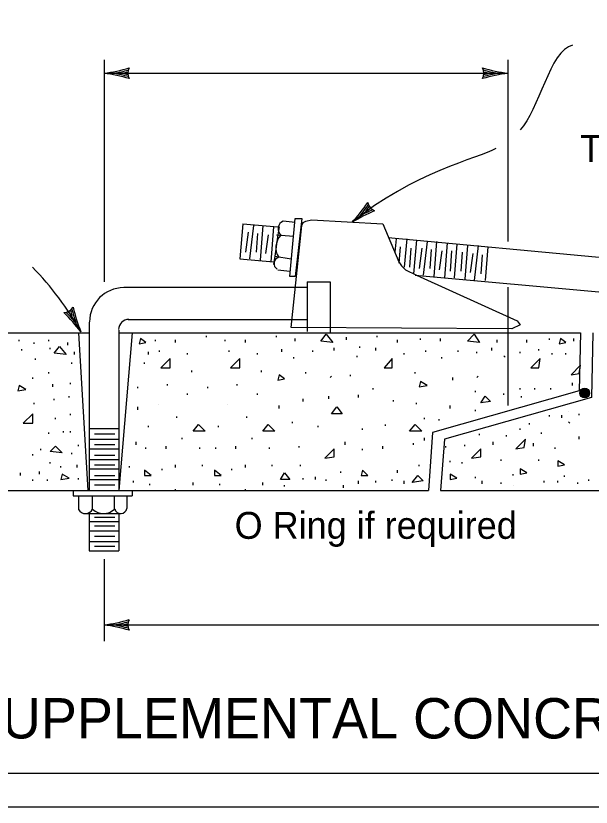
# Model space of a CAD drawing. Extents: x 0 to 390, y 0 to 265.
# Drawn here: x 134.4 to 177.2, y 0 to 58.8 of the extents above; entities that cross this region are included whole.
import ezdxf

# ---------------------------------------------------------------- set-up
doc = ezdxf.new("R2010")
doc.units = 0
doc.layers.add('D_Details', color=7, linetype='Continuous')
doc.layers.add('Default', color=7, linetype='Continuous')

msp = doc.modelspace()

# ---------------------------------------------------------------- linework, layer by layer
at = {"layer": 'D_Details'}
for p, q in [((140.967, 55.541), (140.967, 39.041)), ((170.967, 55.541), (170.967, 42.041)), ((140.967, 54.541), (170.967, 54.541)), ((151.267, 43.341), (151.067, 40.741)), ((151.267, 43.341), (153.867, 43.141)), ((152.067, 43.241), (151.767, 40.741)), ((152.767, 43.241), (152.567, 40.641)), ((153.567, 43.141), (153.367, 40.541)), ((151.667, 42.741), (151.467, 41.241)), ((152.367, 42.641), (152.267, 41.241)), ((153.167, 42.541), (152.967, 41.141)), ((153.767, 42.541), (155.067, 42.441)), ((162.067, 42.341), (200.667, 38.741)), ((162.667, 42.241), (162.567, 41.241)), ((163.467, 42.241), (163.267, 40.141)), ((164.167, 42.141), (163.967, 39.641)), ((164.967, 42.041), (164.667, 39.541)), ((165.667, 42.041), (165.467, 39.441)), ((166.467, 41.941), (166.267, 39.341)), ((167.167, 41.841), (166.967, 39.341)), ((162.967, 41.641), (162.867, 40.441)), ((163.767, 41.541), (163.667, 40.141)), ((164.567, 41.541), (164.367, 40.041)), ((165.267, 41.441), (165.167, 40.041)), ((166.067, 41.341), (165.867, 39.941)), ((166.767, 41.341), (166.667, 39.841)), ((167.567, 41.241), (167.467, 39.841)), ((167.967, 41.741), (167.767, 39.241)), ((168.767, 41.741), (168.467, 39.141)), ((169.467, 41.641), (169.267, 39.141)), ((151.067, 40.741), (153.567, 40.541)), ((153.667, 40.941), (154.867, 40.741)), ((168.367, 41.141), (168.167, 39.741)), ((169.067, 41.041), (168.967, 39.641)), ((164.067, 39.541), (200.067, 36.241)), ((156.067, 39.041), (157.767, 39.041)), ((156.067, 39.041), (156.067, 35.641)), ((157.767, 39.041), (157.767, 35.641)), ((142.467, 38.641), (155.167, 38.641)), ((155.167, 38.641), (156.067, 38.641)), ((170.967, 38.641), (170.967, 29.841)), ((139.867, 36.041), (139.867, 23.541)), ((142.767, 36.241), (154.967, 36.241)), ((154.967, 36.241), (156.067, 36.241)), ((142.067, 35.441), (142.067, 23.541)), ((156.067, 35.641), (156.067, 35.341)), ((157.767, 35.641), (157.767, 35.241)), ((127.267, 35.241), (139.867, 35.241)), ((134.667, 34.641), (134.667, 34.741)), ((136.867, 34.641), (136.867, 34.741)), ((139.067, 35.241), (139.767, 23.541)), ((143.067, 35.241), (142.067, 23.541)), ((142.067, 35.241), (176.367, 35.241)), ((144.779, 34.641), (144.779, 34.741)), ((146.279, 34.541), (146.279, 34.741)), ((148.579, 34.941), (148.579, 35.041)), ((149.967, 34.641), (149.967, 34.741)), ((151.467, 34.541), (151.467, 34.741)), ((153.767, 34.941), (153.767, 35.041)), ((155.167, 34.641), (155.167, 34.841)), ((158.967, 34.741), (158.967, 34.941)), ((161.267, 34.941), (161.267, 35.041)), ((162.767, 34.541), (162.767, 34.741)), ((164.467, 34.741), (164.467, 34.841)), ((165.967, 34.641), (165.967, 34.841)), ((170.167, 34.541), (170.167, 34.741)), ((172.367, 34.541), (172.367, 34.741)), ((174.067, 34.741), (174.067, 34.841)), ((175.867, 34.641), (175.867, 34.841)), ((135.767, 34.441), (135.767, 34.541)), ((136.967, 34.041), (136.967, 34.141)), ((138.267, 34.341), (138.267, 34.541)), ((158.067, 33.941), (158.067, 34.141)), ((159.967, 34.141), (159.967, 34.241)), ((161.167, 33.941), (161.167, 34.141)), ((169.767, 33.941), (169.767, 34.141)), ((134.867, 33.941), (134.867, 34.041)), ((138.767, 33.641), (138.767, 33.841)), ((144.267, 33.641), (144.267, 33.841)), ((145.079, 33.841), (145.079, 33.941)), ((147.179, 33.641), (147.179, 33.741)), ((150.267, 33.841), (150.267, 33.941)), ((152.367, 33.641), (152.367, 33.741)), ((154.167, 33.841), (154.167, 34.041)), ((156.467, 33.841), (156.467, 33.941)), ((159.767, 33.441), (159.767, 33.541)), ((163.267, 33.641), (163.267, 33.741)), ((164.867, 33.841), (164.867, 33.941)), ((167.267, 33.841), (167.267, 33.941)), ((168.667, 33.741), (168.667, 33.841)), ((170.767, 33.441), (170.667, 33.541)), ((171.867, 33.741), (171.867, 33.841)), ((173.267, 33.941), (173.267, 34.041)), ((174.267, 33.641), (174.267, 33.741)), ((175.267, 33.641), (175.267, 33.741)), ((135.867, 33.241), (135.867, 33.341)), ((138.567, 32.941), (138.567, 33.041)), ((143.967, 32.941), (143.967, 33.041)), ((155.067, 33.341), (155.067, 33.441)), ((166.067, 33.341), (166.067, 33.441)), ((147.479, 32.341), (147.479, 32.441)), ((152.667, 32.341), (152.667, 32.441)), ((135.667, 31.841), (135.667, 31.941)), ((136.867, 32.241), (136.867, 32.341)), ((155.967, 32.241), (155.967, 32.341)), ((157.767, 31.941), (157.867, 32.041)), ((159.267, 32.041), (159.267, 32.141)), ((164.067, 32.241), (164.067, 32.341)), ((166.867, 31.741), (166.867, 31.941)), ((168.667, 31.941), (168.767, 32.041)), ((137.167, 31.241), (137.167, 31.441)), ((138.467, 31.441), (138.467, 31.541)), ((143.479, 31.141), (143.479, 31.241)), ((145.679, 31.341), (145.679, 31.441)), ((148.667, 31.141), (148.667, 31.241)), ((150.867, 31.341), (150.867, 31.441)), ((175.767, 31.341), (175.767, 31.541)), ((147.179, 30.641), (147.179, 30.741)), ((152.367, 30.641), (152.367, 30.741)), ((159.867, 30.441), (159.867, 30.641)), ((160.967, 31.041), (160.967, 31.141)), ((168.567, 30.841), (168.567, 30.941)), ((170.667, 30.641), (170.667, 30.741)), ((171.867, 31.041), (171.867, 31.141)), ((172.967, 31.041), (172.967, 31.141)), ((174.167, 31.041), (174.167, 31.141)), ((135.767, 29.941), (135.767, 30.041)), ((137.267, 30.241), (137.267, 30.341)), ((138.367, 30.441), (138.367, 30.541)), ((155.767, 30.141), (155.767, 30.341)), ((157.667, 30.341), (157.667, 30.541)), ((162.467, 30.141), (162.467, 30.241)), ((164.167, 29.941), (164.167, 30.041)), ((171.967, 30.441), (171.967, 30.541)), ((143.467, 29.541), (143.467, 29.741)), ((144.979, 29.941), (144.979, 29.941)), ((150.167, 29.941), (150.167, 29.941)), ((153.967, 29.641), (153.967, 29.841)), ((166.667, 29.641), (166.667, 29.841)), ((168.567, 29.441), (168.567, 29.541)), ((175.467, 29.441), (175.467, 29.441)), ((137.367, 28.841), (137.367, 28.941)), ((138.467, 29.141), (138.467, 29.241)), ((146.379, 28.941), (146.379, 29.041)), ((151.567, 28.941), (151.567, 29.041)), ((164.767, 28.841), (164.767, 28.941)), ((165.867, 28.741), (165.867, 28.841)), ((174.067, 29.041), (174.067, 29.141)), ((174.967, 28.941), (174.967, 29.141)), ((176.267, 29.141), (176.267, 29.241)), ((144.279, 28.241), (144.279, 28.341)), ((149.467, 28.241), (149.467, 28.341)), ((154.967, 28.541), (154.967, 28.641)), ((156.867, 28.241), (156.867, 28.341)), ((161.867, 28.341), (161.867, 28.441)), ((172.567, 28.441), (172.567, 28.541)), ((175.567, 28.541), (175.467, 28.641)), ((136.867, 27.741), (136.867, 27.841)), ((137.967, 27.841), (137.967, 27.941)), ((138.467, 27.841), (138.467, 27.941)), ((139.867, 28.141), (142.067, 28.141)), ((140.267, 27.752), (141.767, 27.752)), ((160.167, 28.041), (160.167, 28.141)), ((168.867, 27.641), (168.867, 27.741)), ((171.867, 28.041), (171.867, 28.141)), ((173.467, 27.741), (173.467, 27.841)), ((139.867, 27.341), (142.067, 27.341)), ((143.367, 26.941), (143.367, 27.141)), ((146.779, 27.341), (146.779, 27.441)), ((151.967, 27.341), (151.967, 27.441)), ((158.867, 26.941), (158.867, 27.141)), ((164.767, 27.241), (164.767, 27.441)), ((169.867, 26.941), (169.867, 27.141)), ((170.867, 27.541), (170.867, 27.641)), ((176.267, 27.341), (176.267, 27.541)), ((136.267, 26.541), (136.267, 26.641)), ((139.067, 26.841), (139.067, 26.941)), ((139.867, 26.641), (142.067, 26.641)), ((140.267, 26.952), (141.767, 26.952)), ((144.079, 26.641), (144.079, 26.741)), ((145.579, 26.641), (145.579, 26.841)), ((148.079, 26.641), (148.079, 26.741)), ((149.267, 26.641), (149.267, 26.741)), ((150.767, 26.641), (150.767, 26.841)), ((153.267, 26.641), (153.267, 26.741)), ((155.467, 26.741), (155.467, 26.841)), ((160.167, 26.541), (160.167, 26.641)), ((161.667, 26.641), (161.667, 26.841)), ((163.967, 26.941), (163.967, 27.041)), ((166.367, 26.741), (166.367, 26.841)), ((167.767, 26.841), (167.767, 26.941)), ((172.867, 26.841), (172.867, 27.041)), ((174.467, 26.641), (174.467, 26.741)), ((135.667, 26.141), (135.667, 26.241)), ((138.567, 26.241), (138.567, 26.341)), ((140.267, 26.152), (141.767, 26.152)), ((136.967, 25.541), (136.967, 25.641)), ((137.767, 25.241), (137.767, 25.341)), ((138.967, 25.241), (138.967, 25.441)), ((139.867, 25.841), (142.067, 25.841)), ((140.267, 25.452), (141.767, 25.452)), ((142.867, 25.241), (142.867, 25.341)), ((146.279, 25.241), (146.279, 25.441)), ((148.279, 25.341), (148.279, 25.441)), ((151.467, 25.241), (151.467, 25.441)), ((153.467, 25.341), (153.467, 25.441)), ((155.567, 25.341), (155.567, 25.441)), ((164.367, 25.341), (164.367, 25.441)), ((166.667, 25.641), (166.667, 25.741)), ((167.567, 25.541), (167.567, 25.641)), ((170.467, 25.741), (170.467, 25.841)), ((173.267, 25.741), (173.267, 25.841)), ((134.767, 24.641), (134.767, 24.841)), ((136.167, 24.741), (136.167, 24.941)), ((139.867, 25.141), (142.067, 25.141)), ((145.279, 25.041), (145.279, 25.141)), ((150.467, 25.041), (150.467, 25.141)), ((158.567, 24.841), (158.567, 24.941)), ((162.767, 24.841), (162.767, 25.041)), ((171.367, 24.641), (171.367, 24.741)), ((135.667, 24.241), (135.667, 24.341)), ((136.767, 24.241), (136.767, 24.341)), ((139.067, 24.341), (139.067, 24.441)), ((139.867, 24.341), (142.067, 24.341)), ((140.267, 24.652), (141.767, 24.652)), ((143.167, 24.141), (143.167, 24.241)), ((147.579, 23.941), (147.579, 24.141)), ((152.767, 23.941), (152.767, 24.141)), ((155.767, 24.341), (155.767, 24.441)), ((156.667, 24.341), (156.667, 24.541)), ((157.467, 24.241), (157.467, 24.341)), ((159.867, 24.041), (159.867, 24.241)), ((161.167, 24.141), (161.167, 24.241)), ((162.367, 24.241), (162.367, 24.341)), ((163.267, 24.041), (163.267, 24.241)), ((168.567, 24.441), (168.567, 24.541)), ((169.067, 24.041), (169.067, 24.241)), ((170.467, 24.041), (170.467, 24.141)), ((173.667, 24.141), (173.667, 24.241)), ((174.667, 24.141), (174.667, 24.241)), ((175.167, 24.541), (175.167, 24.641)), ((176.167, 24.041), (176.167, 24.141)), ((176.967, 24.241), (176.967, 24.341)), ((127.267, 23.541), (165.067, 23.541)), ((138.667, 23.541), (143.067, 23.541)), ((138.667, 23.541), (138.667, 23.141)), ((139.967, 23.541), (142.067, 23.541)), ((140.267, 23.952), (141.767, 23.952)), ((143.067, 23.541), (143.067, 23.141)), ((144.379, 23.941), (144.379, 24.041)), ((146.279, 23.541), (146.279, 23.641)), ((149.567, 23.941), (149.567, 24.041)), ((151.467, 23.541), (151.467, 23.641)), ((154.367, 23.841), (154.367, 23.941)), ((158.767, 23.741), (158.767, 23.941)), ((165.967, 23.541), (212.067, 23.541)), ((171.367, 23.941), (171.367, 23.941)), ((138.667, 23.141), (143.067, 23.141)), ((139.067, 23.141), (139.067, 22.117)), ((140.12, 22.152), (140.12, 23.141)), ((141.757, 22.173), (141.757, 23.141)), ((142.667, 23.141), (142.667, 22.205)), ((139.532, 21.822), (142.232, 21.822)), ((139.867, 21.841), (139.867, 19.041)), ((142.067, 21.841), (142.067, 19.041)), ((139.867, 21.241), (142.067, 21.241)), ((140.267, 21.563), (141.767, 21.563)), ((140.267, 20.905), (141.767, 20.905)), ((139.867, 20.541), (142.067, 20.541)), ((140.267, 20.141), (141.767, 20.141)), ((139.867, 19.741), (142.067, 19.741)), ((139.867, 19.041), (142.067, 19.041)), ((140.267, 19.387), (141.767, 19.387)), ((140.967, 18.441), (140.967, 12.341)), ((140.967, 13.541), (201.867, 13.541))]:
    msp.add_line(p, q, dxfattribs=at)
for points in [[(155.167, 43.441), (154.267, 43.541)], [(155.167, 43.741), (155.667, 43.741), (155.167, 39.441), (154.767, 39.441), (155.167, 43.741)], [(154.867, 35.641), (155.667, 43.241), (155.767, 43.441), (155.967, 43.541), (156.367, 43.641), (161.667, 43.341), (162.867, 40.541), (163.067, 40.241), (163.367, 39.941), (164.167, 39.541), (171.667, 36.141), (171.867, 35.841), (171.267, 35.541), (154.867, 35.641)], [(153.967, 43.141), (153.867, 42.541), (153.667, 40.941), (153.567, 40.341)], [(153.867, 39.941), (154.767, 39.841)], [(176.367, 35.241), (176.267, 30.941), (165.367, 27.841), (165.067, 23.541)], [(177.267, 35.241), (177.167, 30.441), (166.267, 27.341), (165.967, 23.541)]]:
    msp.add_lwpolyline(points, dxfattribs=at)
for points in [[(143.567, 34.441), (144.067, 34.541), (143.667, 34.841)], [(157.067, 34.641), (157.467, 35.141), (157.967, 34.541)], [(167.967, 34.641), (168.467, 35.141), (168.867, 34.541)], [(174.767, 34.441), (175.267, 34.541), (174.867, 34.841)], [(137.267, 33.741), (137.667, 34.241), (138.167, 33.641)], [(145.879, 32.641), (145.879, 33.341), (145.179, 32.641)], [(151.067, 32.641), (151.067, 33.341), (150.367, 32.641)], [(162.367, 32.641), (162.367, 33.341), (161.767, 32.641)], [(173.267, 32.641), (173.367, 33.341), (172.667, 32.641)], [(176.267, 32.241), (176.367, 32.841), (175.667, 32.141)], [(153.867, 31.741), (154.367, 31.841), (153.967, 32.141)], [(134.567, 30.941), (135.167, 31.041), (134.667, 31.341)], [(164.367, 31.241), (164.967, 31.341), (164.467, 31.641)], [(168.967, 30.041), (169.267, 30.541), (169.667, 30.141)], [(157.867, 29.241), (158.267, 29.741), (158.667, 29.241)], [(135.667, 28.541), (135.667, 29.241), (134.967, 28.541)], [(147.579, 27.941), (147.979, 28.441), (148.479, 27.941)], [(152.767, 27.941), (153.167, 28.441), (153.667, 27.941)], [(163.667, 27.941), (164.067, 28.441), (164.567, 27.941)], [(172.167, 26.741), (172.267, 27.341), (171.567, 26.641)], [(136.967, 26.441), (137.367, 26.841), (137.867, 26.341)], [(158.067, 26.041), (158.067, 26.641), (157.367, 25.941)], [(168.967, 26.041), (168.967, 26.641), (168.267, 25.941)], [(174.667, 25.341), (175.167, 25.441), (174.667, 25.741)], [(137.767, 24.341), (138.367, 24.441), (137.867, 24.741)], [(143.979, 24.641), (144.479, 24.641), (143.979, 25.041)], [(149.167, 24.641), (149.667, 24.641), (149.167, 25.041)], [(154.067, 24.341), (154.367, 24.841), (154.767, 24.341)], [(160.067, 24.641), (160.567, 24.641), (160.167, 25.041)], [(166.667, 24.341), (167.167, 24.441), (166.667, 24.741)], [(171.867, 24.741), (172.367, 24.841), (171.867, 25.141)], [(163.867, 24.141), (164.267, 24.641), (164.667, 24.241)]]:
    msp.add_lwpolyline(points, close=True, dxfattribs=at)
for centre, radius in [((176.676, 30.78), 0.361), ((176.68, 30.774), 0.333), ((176.673, 30.786), 0.289), ((176.665, 30.804), 0.238), ((176.676, 30.812), 0.2), ((176.671, 30.814), 0.165), ((176.669, 30.82), 0.128), ((176.673, 30.834), 0.0991), ((176.675, 30.838), 0.0634), ((176.676, 30.84), 0.0199)]:
    msp.add_circle(centre, radius, dxfattribs=at)
for centre, radius, start, end in [((139.01, 68.467), 14.063, 278, 285.81169), ((139.01, 68.467), 14.188, 281.00099, 285.43008), ((143.622, 54.541), 0.874, 153.215, 206.78499), ((172.924, 68.467), 14.063, 254.18653, 262), ((168.312, 54.541), 0.874, 333.215, 26.78499), ((172.924, 68.467), 14.188, 254.56992, 258.99901), ((139.01, 40.615), 14.063, 74.18653, 82), ((139.01, 40.615), 14.188, 74.56992, 78.99901), ((139.01, 68.467), 14.313, 283.35937, 285.17092), ((139.01, 40.615), 14.313, 74.82908, 76.64064), ((172.924, 40.615), 14.063, 98, 105.81169), ((172.924, 40.615), 14.188, 101.00099, 105.43008), ((172.924, 68.467), 14.313, 254.82908, 256.64064), ((172.924, 40.615), 14.313, 103.35937, 105.17092), ((149.011, 52.955), 14.063, 317.4278, 325.23949), ((149.011, 52.955), 14.188, 320.4288, 324.85788), ((161.417, 45.127), 0.874, 192.64281, 246.2128), ((166.699, 31.441), 14.063, 113.61433, 121.4278), ((166.699, 31.441), 14.188, 113.99773, 118.42681), ((149.011, 52.955), 14.313, 322.78717, 324.59873), ((166.699, 31.441), 14.313, 114.25688, 116.06844), ((154.515, 42.983), 0.621, 112.43252, 230.07828), ((154.991, 41.595), 1.269, 134.57304, 214.62405), ((154.069, 40.401), 0.479, 103.82353, 240.50616), ((118.445, 23.522), 23.921, 29.56096, 44.00876), ((142.435, 36.07), 2.54, 90, 180), ((137.942, 37.633), 0.874, 272.77596, 326.34595), ((152.331, 40.491), 14.063, 193.74749, 201.56096), ((128.105, 26.751), 14.063, 37.56096, 45.37264), ((128.105, 26.751), 14.188, 40.56195, 44.99104), ((128.105, 26.751), 14.313, 42.92033, 44.73188), ((152.331, 40.491), 14.313, 194.39004, 196.20159), ((152.331, 40.491), 14.188, 194.13088, 198.55996), ((142.812, 35.49), 0.762, 90, 180), ((139.583, 22.418), 0.598, 210.26043, 333.54113), ((140.927, 22.972), 1.152, 225.41592, 315.15717), ((142.208, 22.288), 0.466, 195.92594, 349.72424), ((139.01, 27.467), 14.063, 278, 285.81169), ((139.01, -0.385), 14.063, 74.18653, 82), ((139.01, 27.467), 14.188, 281.00099, 285.43008), ((139.01, -0.385), 14.188, 74.56992, 78.99901), ((139.01, 27.467), 14.313, 283.35937, 285.17092), ((139.01, -0.385), 14.313, 74.82908, 76.64064), ((143.622, 13.541), 0.874, 153.215, 206.78499)]:
    msp.add_arc(centre, radius, start, end, dxfattribs=at)
for points in [[(175.767, 56.641), (174.067, 56.241), (173.267, 51.741), (171.867, 50.341)], [(170.067, 48.941), (168.767, 48.241), (163.867, 47.141), (159.367, 43.441)]]:
    msp.add_open_spline(points, degree=3, dxfattribs=at)
at = {"layer": 'Default'}
for points in [[(0, 265), (326.25, 265), (326.25, 255), (390, 255), (390, 37.5), (315, 37.5), (315, 0), (0, 0)], [(0, 262.5), (326.25, 262.5), (326.25, 252.5), (390, 252.5), (390, 40), (315, 40), (315, 2.5), (0, 2.5)]]:
    msp.add_lwpolyline(points, close=True, dxfattribs=at)

# ---------------------------------------------------------------- texts
at = {"layer": 'D_Details'}
for s, height, p in [('Tapered holes permitted', 2, (176.329, 47.943)), ('O Ring if required', 2, (150.668, 19.943)), ('SUPPLEMENTAL CONCRETE PIPE TIE', 3, (130.702, 5.105))]:
    msp.add_text(s, height=height, dxfattribs=at).set_placement(p)

doc.saveas('drawing.dxf')
